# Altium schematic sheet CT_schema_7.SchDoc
size 371 x 336 mm
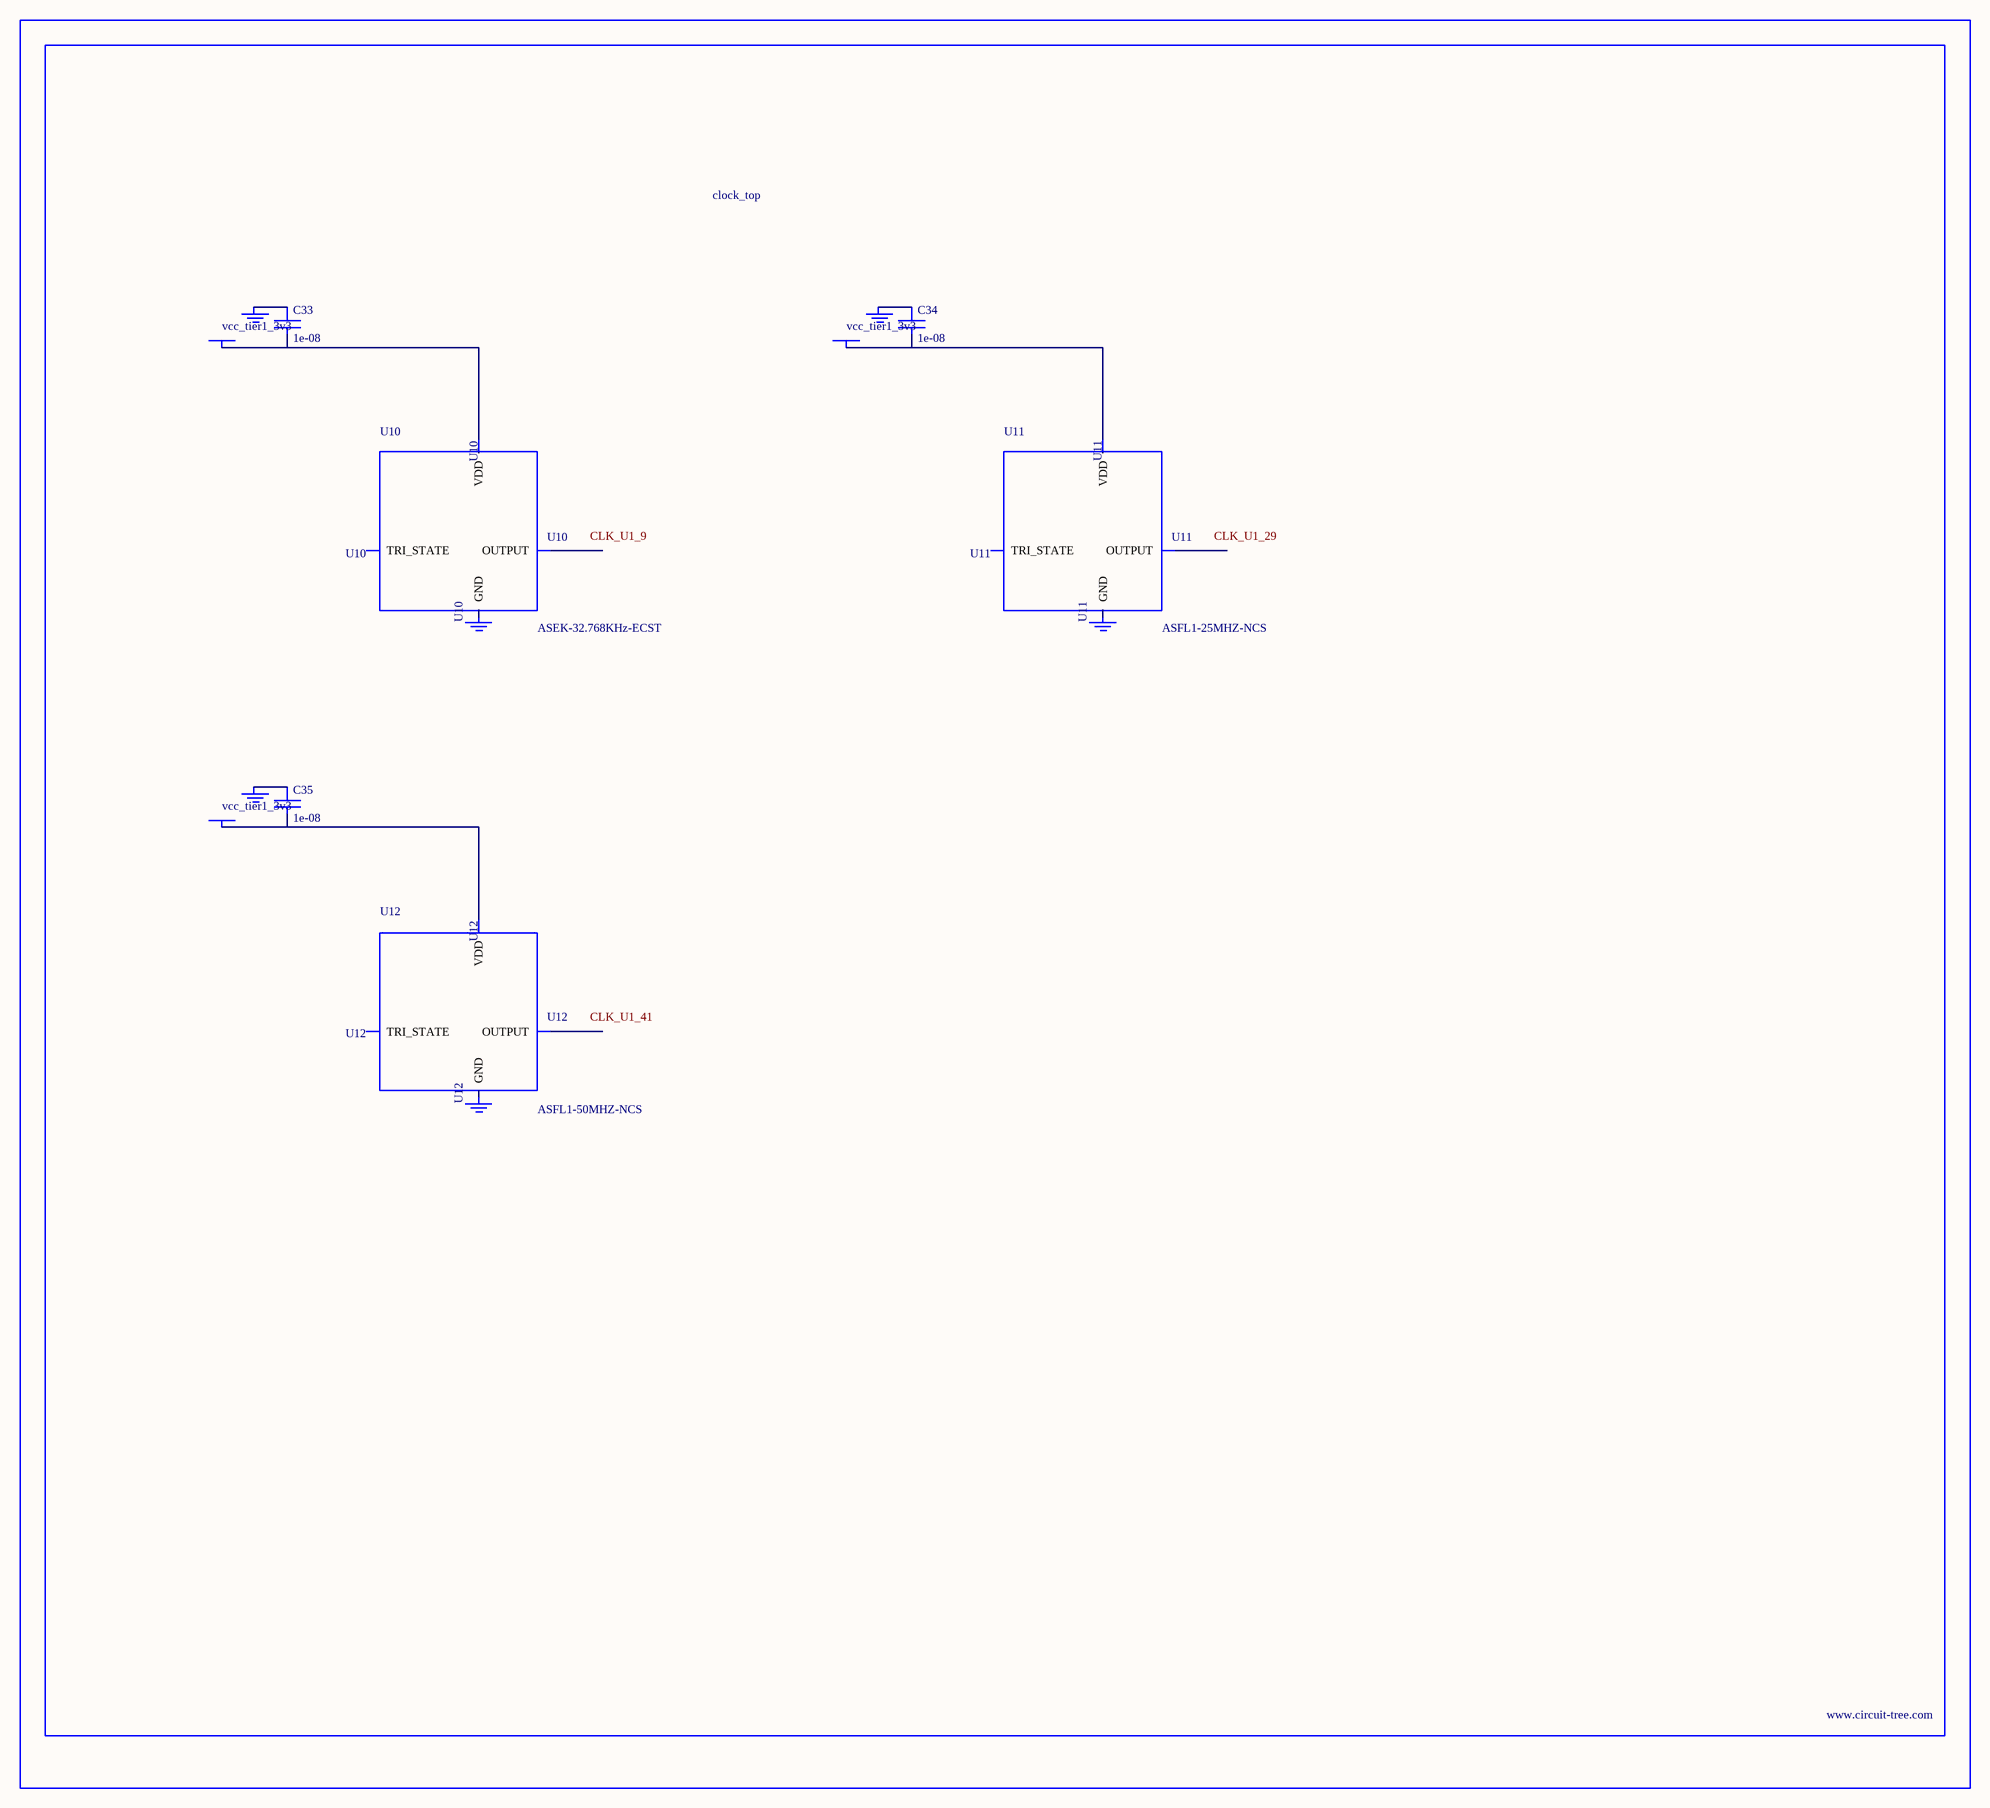
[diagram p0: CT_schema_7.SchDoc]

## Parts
BORDER6  (no value)
C33  1e-08  [C0402]
C34  1e-08  [C0402]
C35  1e-08  [C0402]
GND_INSTANCE_6_0  (no value)
GND_INSTANCE_6_1  (no value)
GND_INSTANCE_6_2  (no value)
GND_INSTANCE_6_3  (no value)
GND_INSTANCE_6_4  (no value)
GND_INSTANCE_6_5  (no value)
POWER_INSTANCE_6_0  vcc_tier1_3v3
POWER_INSTANCE_6_1  vcc_tier1_3v3
POWER_INSTANCE_6_2  vcc_tier1_3v3
U10  ASEK-32.768KHz-ECST  [ASEK]
U11  ASFL1-25MHZ-NCS  [ASFL1]
U12  ASFL1-50MHZ-NCS  [ASFL1]

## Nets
NetC33_1: C33.1 GND_INSTANCE_6_0.0(GND)
NetC33_2: C33.2 POWER_INSTANCE_6_0.0(PWR) U10.4(VDD)
NetC34_1: C34.1 GND_INSTANCE_6_2.0(GND)
NetC34_2: C34.2 POWER_INSTANCE_6_1.0(PWR) U11.4(VDD)
NetC35_1: C35.1 GND_INSTANCE_6_4.0(GND)
NetC35_2: C35.2 POWER_INSTANCE_6_2.0(PWR) U12.4(VDD)

Not connected (* = marked no-connect by the designer): GND_INSTANCE_6_1 0(GND); GND_INSTANCE_6_3 0(GND); GND_INSTANCE_6_5 0(GND); U10 1(TRI_STATE) 2(GND) 3(OUTPUT); U11 1(TRI_STATE) 2(GND) 3(OUTPUT); U12 1(TRI_STATE) 2(GND) 3(OUTPUT)

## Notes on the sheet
- Labels drawn without touching a wire or pin: CLK_U1_9, CLK_U1_29, CLK_U1_41

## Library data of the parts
BORDER6 = BORDER_PAGE6
C33-C35 = C0402C103K3RAC
GND_INSTANCE_6_0-GND_INSTANCE_6_5 = GND
POWER_INSTANCE_6_0-POWER_INSTANCE_6_2 = PWR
